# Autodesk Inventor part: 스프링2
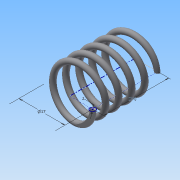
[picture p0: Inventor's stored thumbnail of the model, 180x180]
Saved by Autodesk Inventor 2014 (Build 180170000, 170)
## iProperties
Created: 2016-01
Part Number: 스프링2
Material: 강철, 탄소
Document SubType Name: Modeling
Designer: Administrator
Density: 1 g/cm^3
Appearance: 반연마
Author: Administrator
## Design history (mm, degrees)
sketch "스케치1"
  geometry: L1 (0, 0)-(8.5, 0); L2 (8.5, 0)-(8.5, 17.5); L3 (8.5, 17.5)-(0, 17.5); L4 (0, 17.5)-(0, 0); C1 r 1 at (8.5, 0)
  constraints: 8 end point, 2 parallel, 1 centre point, 1 coincident, 1 horizontal, 1 perpendicular
  dimensions: "d0" = 17 diameter of L2 L4; "d1" = 17.5 distance of L1.end L2.end (derived); "d2" = 2 diameter of C1
feature "코일1" sketch "스케치1" pitch "d3" = 10; turns "d5" = 5; dims "d4" = 17.5 (= d1), "d6" = 0, angle "d7" = 90 deg, angle "d8" = 90 deg, "d9" = 0, "d10" = 0
node "작업 평면2"
  node "작업 평면1"
sketch "스케치2"
  geometry: L1 (-9.5, 0)-(-7.5, 0) reference; 1 further point
  constraints: 1 horizontal alignment
extrude "돌출1" cut sketch "스케치2" stored distance "d13" = 10; taper "d14" = 0 deg
sketch "스케치3"
  geometry: L1 (-7.5, 0)-(-9.5, 0) reference; 1 further point
  constraints: 1 horizontal alignment
extrude "돌출2" cut sketch "스케치3" stored distance "d15" = 10; taper "d16" = 0 deg
node "솔리드1"
node "절단 모서리 투영1"
node "절단 모서리 투영2"
other parameters: "d11" = 0, "d12" = 17.5 (= d1)
